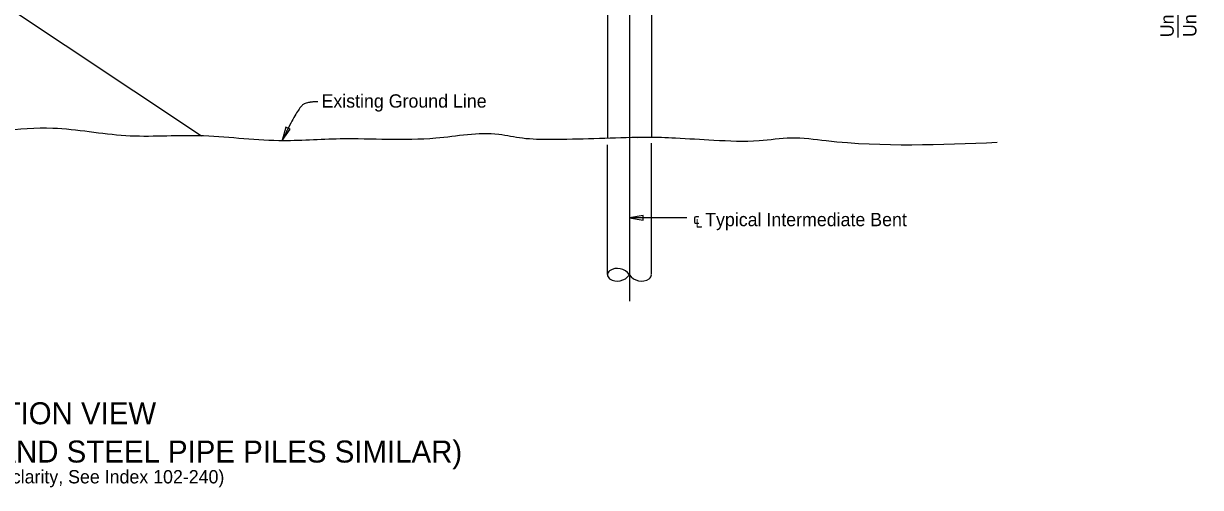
# Model space of a CAD drawing. Extents: x 3 to 58.1, y 3.3 to 34.2.
# Drawn here: x 28.56 to 55.32, y 3.34 to 13.88 of the extents above; entities that cross this region are included whole.
import ezdxf

# ---------------------------------------------------------------- set-up
doc = ezdxf.new("R2010")
doc.units = 0
for name, color, linetype in [('CL_Minor', 7, 'Continuous'), ('Dimension', 7, 'Continuous'), ('GroundLines', 7, 'Continuous'), ('Miscellaneous', 7, 'Continuous'), ('TextStructures', 7, 'Continuous'), ('Wood', 7, 'Continuous'), ('Wood_h', 7, 'Continuous')]:
    doc.layers.add(name, color=color, linetype=linetype)

msp = doc.modelspace()

# ---------------------------------------------------------------- linework, layer by layer
at = {"layer": 'CL_Minor'}
msp.add_line((42.335, 22.925), (42.335, 7.572), dxfattribs=at)
at = {"layer": 'Dimension'}
for p, q in [((54.802, 25.116), (54.802, 13.565)), ((43.641, 9.469), (42.335, 9.469))]:
    msp.add_line(p, q, dxfattribs=at)
for points in [[(34.44, 11.221), (34.62, 11.481), (34.525, 11.526)], [(42.335, 9.469), (42.647, 9.416), (42.647, 9.522)]]:
    msp.add_lwpolyline(points, close=True, dxfattribs=at)
msp.add_open_spline([(35.25, 12.105), (35.083, 12.105), (34.811, 12.011), (34.44, 11.221)], degree=2, dxfattribs=at)
at = {"layer": 'GroundLines'}
for points in [[(42.508, 11.295), (40.547, 11.246), (39.901, 11.274), (39.367, 11.359), (37.934, 11.274), (35.758, 11.258), (34.367, 11.218), (32.541, 11.33), (30.884, 11.33), (29.227, 11.499), (26.896, 11.302), (23.974, 11.274), (20.435, 11.106), (19.569, 11.183)], [(42.508, 11.295), (42.541, 11.296), (43.063, 11.296), (43.381, 11.283)], [(43.381, 11.283), (44.252, 11.234), (45.283, 11.221), (46.009, 11.285), (46.811, 11.221), (50.698, 11.183)]]:
    msp.add_spline(points, degree=3, dxfattribs=at)
at = {"layer": 'Miscellaneous'}
msp.add_line((19.956, 19.761), (32.606, 11.328), dxfattribs=at)
at = {"layer": 'Wood'}
for p, q in [((41.835, 20.842), (41.835, 11.278)), ((42.835, 20.842), (42.835, 11.299))]:
    msp.add_line(p, q, dxfattribs=at)
at = {"layer": 'Wood_h'}
for p, q in [((41.835, 8.177), (41.835, 11.128)), ((42.835, 8.177), (42.835, 11.163))]:
    msp.add_line(p, q, dxfattribs=at)
for centre, radius, start, end in [((42.063, 7.988), 0.329, 34.3251, 123.0426), ((41.942, 8.174), 0.107, 122.6152, 179.9979), ((41.942, 8.174), 0.107, 179.9979, 237.3848), ((42.063, 8.359), 0.329, 236.955, 325.6725), ((42.606, 8.359), 0.329, 214.3153, 303.0328), ((42.728, 8.174), 0.107, 302.6152, 0.0021)]:
    msp.add_arc(centre, radius, start, end, dxfattribs=at)

# ---------------------------------------------------------------- texts
at = {"layer": 'Dimension'}
for s, p in [('Underside of Expansion Bearing', (55.225, 13.575)), ('Underside of Fixed Bearing', (54.709, 13.57))]:
    msp.add_text(s, height=0.3024, rotation=90, dxfattribs=at).set_placement(p)
at = {"layer": 'TextStructures'}
for s, height, p in [('Existing Ground Line', 0.3024, (35.334, 11.97)), ('℄ Typical Intermediate Bent', 0.3024, (43.78, 9.276)), ('ELEVATION VIEW', 0.5, (25.928, 4.776)), ('(TIMBER PILES SHOWN, STEEL H PILES AND STEEL PIPE PILES SIMILAR)', 0.5, (14.939, 3.906)), ('(Thrie-Beam Panel not shown for clarity, See Index 102-240)', 0.3024, (22.247, 3.432))]:
    msp.add_text(s, height=height, dxfattribs=at).set_placement(p)

doc.saveas('drawing.dxf')
